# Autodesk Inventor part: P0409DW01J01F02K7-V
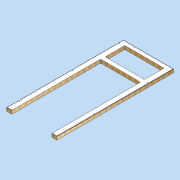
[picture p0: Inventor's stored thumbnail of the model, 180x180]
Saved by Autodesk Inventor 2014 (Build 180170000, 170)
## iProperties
Created: 2011-04
Part Number: P0409DW01J01F02K7-V
Document SubType Name: Modeling
Designer: david.appleford
Density: 1 g/cm^3
Description: 1w x 2w  01 Panel - 6 Locks
Cost Center: £143.00
Mass: 64418.2 g
Surface Area: 27815.6 cm^2
Volume: 64418.2 cm^3
Material: Generic
Appearance: Wood (Pine)
Justset: False
Title: 1w x 2w  01 Panel - 6 Locks
Author: david.appleford
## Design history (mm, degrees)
sketch "Sketch1"
  geometry: L1 (0, 0)-(1220, 0); L2 (1220, 0)-(1220, 2745); L3 (1220, 2745)-(0, 2745); L4 (0, 2745)-(0, 0); L5 (34, 2711)-(1186, 2711); L6 (1186, 2711)-(1186, 34); L7 (1186, 34)-(34, 34); L8 (34, 34)-(34, 2711)
  constraints: 16 end point, 4 parallel, 2 perpendicular, 1 horizontal, 3 other
  dimensions: "d0" = 1220 distance between parallel lines of L2 L4 (= w); "d1" = 2745 distance between parallel lines of L1 L3 (= 2.25 x w); "d2" = 34 distance between parallel lines of L5 L3 (= 0.5 x t); "d29" = 2677 distance between parallel lines of L7 L5 (derived); "d30" = 1152 distance between parallel lines of L6 L8 (derived)
extrude "Extrusion1" new body sketch "Sketch1" distance "d3" = 68 (= t); taper "d4" = 0 deg
sketch "Sketch2"
  geometry: L1 (1186, 2711)-(1186, 34) reference; L2 (34, 2711)-(1186, 2711) reference; L3 (34, 34)-(34, 2711) reference; L4 (1186, 34)-(34, 34) reference; L5 (1176, 2701)-(1176, 44); L6 (1176, 44)-(44, 44); L7 (44, 44)-(44, 2701); L8 (44, 2701)-(1176, 2701); 1 further point
  constraints: 8 end point, 3 other
  dimensions: "d5" = 10 distance between parallel lines of L8 L2
extrude "Extrusion2" join sketch "Sketch2" distance "d6" = 6 (= sw); taper "d7" = 0 deg
sketch "Sketch3"
  geometry: L1 (-44, 2701)-(-1176, 2701) reference; L2 (-1176, 2701)-(-1176, 44) reference; L3 (-44, 44)-(-44, 2701) reference; L4 (-1176, 44)-(-44, 44) reference; 1 further point
extrude "Extrusion3" join sketch "Sketch3" distance "d8" = 6 (= sw); taper "d9" = 0 deg
sketch "Sketch4"
  geometry: L1 (34, 2711)-(1186, 2711) reference; L2 (1186, 2711)-(1186, 34) reference; L3 (1186, 34)-(34, 34) reference; L4 (34, 34)-(34, 2711) reference; 8 further points
  constraints: 3 vertical alignment
  dimensions: "d10" = 28 distance from line of point (305, 2683) L1 (= k); "d12" = 28 distance from line of L3 point (915, 62) (= k); "d13" = 28 distance from line of point (62, 305) L4 (= k); "d14" = 305 horizontal distance of point (305, 2683) point (0, 0) (= 0.25 x w); "d15" = 610 horizontal distance of point (915, 62) point (305, 2683) (= 0.5 x w); "d16" = 305 vertical distance of point (62, 305) point (0, 0) (= 0.25 x w); "d17" = 1220 distance of point (62, 305) point (62, 1525) (= w); "d19" = 610 vertical distance of point (1158, 915) point (62, 305) (= 0.5 x w); "d20" = 1220 distance of point (1158, 915) point (1158, 2135) (= w); "d31" = 1067.5 distance of point (62, 1525) point (62, 2592.5)
hole "Hole1" sketch "Sketch4" at (305, 2683), (62, 1525), (62, 305), (1158, 2135), (1158, 915), (915, 62), (62, 2592.5) diameter "d22" = 12 (= hd); stored, may be unused: countersink angle "d26" = 90 deg, drill point angle "d28" = 118 deg; dims "d23" = 6, "d24" = 4, "d25" = 2, "d27" = 8
sketch "Sketch5"
  geometry: L1 (172, 2069)-(1048, 2069); L2 (1068, 2049)-(1068, 34); L3 (1068, 34)-(152, 34); L4 (152, 34)-(152, 2049); L5 (1186, 34)-(34, 34) reference; L6 (34, 34)-(34, 2711) reference; L7 (1186, 2711)-(1186, 34) reference; L8 (180, 2615)-(1040, 2615); L9 (1060, 2595)-(1060, 2185); L10 (1040, 2165)-(180, 2165); L11 (160, 2185)-(160, 2595); L12 (34, 2711)-(1186, 2711) reference; A1 r 20 centre (172, 2049) between (172, 2069) and (152, 2049); A2 r 20 centre (1048, 2049) between (1068, 2049) and (1048, 2069); A3 r 20 centre (180, 2595) between (180, 2615) and (160, 2595); A4 r 20 centre (1040, 2595) between (1060, 2595) and (1040, 2615); A5 r 20 centre (1040, 2185) between (1040, 2165) and (1060, 2185); A6 r 20 centre (180, 2185) between (160, 2185) and (180, 2165); 1 further point
  constraints: 16 end point, 12 point on circle, 12 tangent, 6 centre point, 4 equal radius, 1 collinear
  dimensions: "d32" = 916 distance between parallel lines of L2 L4; "d33" = 2035 distance between parallel lines of L3 L1; "d34" = 118 distance between parallel lines of L6 L4 (= -0.5 x d32 + 0.5 x d35); "d35" = 1152 distance between parallel lines of L7 L6 (derived); "d36" = 20 radius of A1; "d39" = 900 distance between parallel lines of L9 L11; "d40" = 8 distance between parallel lines of L4 L11 (= -0.5 x d39 + 0.5 x d32); "d41" = 450 distance between parallel lines of L10 L8; "d42" = 96 distance between parallel lines of L12 L8 (= -0.5 x d41 + 0.5 x d43); "d43" = 642 distance between parallel lines of L1 L12 (derived); "d44" = 20 radius of A3
extrude "Extrusion4" cut sketch "Sketch5" stored distance "d37" = 10; taper "d38" = 0 deg
body "Solid1"
node "Projected Loop1"
other parameters: "w" = 1220 [user parameter; used in 8 equation terms], "t" = 68 [user parameter; used in 2 equation terms], "e" = 16 [user parameter], "sw" = 6 [user parameter; used in 2 equation terms], "sc" = 9 [user parameter], "sf" = 12 [user parameter], "k" = 28 [user parameter; used in 3 equation terms], "hd" = 12 [user parameter; used in 1 equation term]
